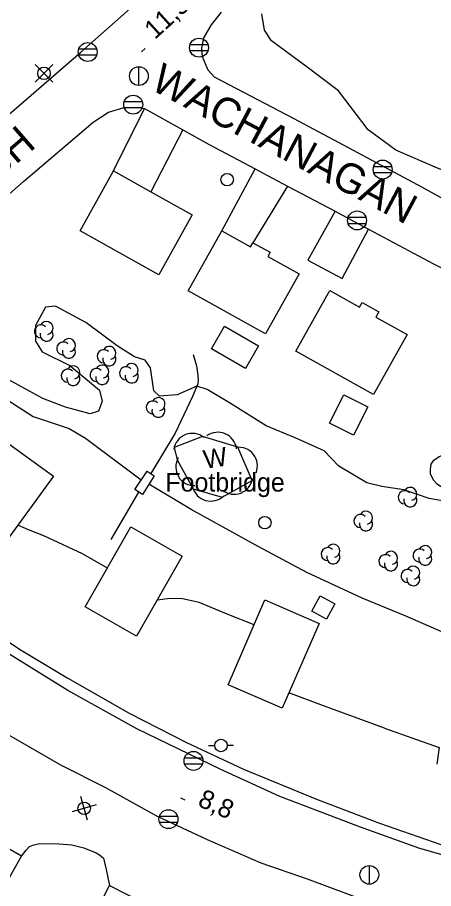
# Model space of a CAD drawing. Extents: x 646142 to 649934, y 5874075 to 5876351.
# Drawn here: x 646717.7 to 646784.5, y 5874712.5 to 5874852.4 of the extents above; entities that cross this region are included whole.
import ezdxf

# ---------------------------------------------------------------- set-up
doc = ezdxf.new("R2010")
doc.units = 0
for name, color, linetype in [('Niveau 1', 7, 'Continuous'), ('Niveau 15', 7, 'Continuous'), ('Niveau 19', 7, 'Continuous'), ('Niveau 2', 7, 'Continuous'), ('Niveau 21', 7, 'Continuous'), ('Niveau 22', 7, 'Continuous'), ('Niveau 26', 7, 'Continuous'), ('Niveau 3', 7, 'Continuous'), ('Niveau 31', 7, 'Continuous'), ('Niveau 36', 7, 'Continuous'), ('Niveau 4', 7, 'Continuous'), ('Niveau 44', 7, 'Continuous')]:
    doc.layers.add(name, color=color, linetype=linetype)

msp = doc.modelspace()

# ---------------------------------------------------------------- linework, layer by layer
at = {"layer": 'Niveau 1'}
for points in [[(646739.02, 5874796.13), (646738.16, 5874797.35), (646736.48, 5874797.92), (646733.65, 5874799.69), (646728.67, 5874803.4), (646723.78, 5874806.06), (646722.16, 5874805.88), (646720.59, 5874802.94), (646720.57, 5874800.42), (646721.64, 5874798.69), (646726.09, 5874796.52), (646730.85, 5874792.56), (646731.29, 5874790.78), (646730.66, 5874789.2), (646729.36, 5874788.75), (646725.41, 5874789.84), (646721.74, 5874791.19), (646716.17, 5874794.27)], [(646787.38, 5874774.53), (646783.77, 5874775.18), (646779.69, 5874776.56), (646776.14, 5874777.1), (646773.76, 5874777.67), (646769.28, 5874780.36), (646766.92, 5874782.81), (646762.25, 5874784.9), (646757.6, 5874786.82), (646751.69, 5874790.51), (646748.13, 5874792.63), (646746.45, 5874793.2), (646743.3, 5874791.78), (646740.45, 5874791.56), (646739.56, 5874792.42), (646739.02, 5874796.13)]]:
    msp.add_lwpolyline(points, dxfattribs=at)
at = {"layer": 'Niveau 19'}
for points in [[(646733.07, 5874827.74), (646738.07, 5874837.74)], [(646744.19, 5874834.36), (646739.1, 5874824.38)], [(646750.45, 5874818.15), (646755.8, 5874828.09)], [(646761.02, 5874825.31), (646755.47, 5874816.22)], [(646768.65, 5874821.27), (646764.29, 5874813.44), (646769.78, 5874810.48), (646774.04, 5874818.4)], [(646732.1, 5874763.98), (646728.1, 5874766.28), (646721.89, 5874769.19), (646719.45, 5874770.15), (646717.72, 5874770.86)], [(646755.67, 5874754.9), (646751.34, 5874756.58), (646746.85, 5874758.45), (646744.15, 5874759.04), (646742.19, 5874759.08), (646740.08, 5874758.84)], [(646776.57, 5874738.28), (646766.36, 5874742.03), (646761.24, 5874743.95)], [(646776.57, 5874738.28), (646785.37, 5874735.17), (646784.96, 5874732.52)], [(646718.33, 5874717.72), (646719.05, 5874718.72), (646719.62, 5874719.27), (646720.13, 5874719.52), (646721.23, 5874719.78), (646724.31, 5874719.71), (646726.38, 5874719.54), (646728.33, 5874719.07), (646730.32, 5874718.3), (646730.84, 5874717.97), (646731.49, 5874717.4), (646731.93, 5874715.59), (646732.45, 5874713.02)]]:
    msp.add_lwpolyline(points, dxfattribs=at)
at = {"layer": 'Niveau 2'}
msp.add_lwpolyline([(646802.57, 5874853.89), (646806.87, 5874850.43), (646809.49, 5874846.9), (646809.96, 5874844.71), (646809.71, 5874842.12), (646808.76, 5874840.24), (646805.83, 5874835.56), (646801.62, 5874829.39), (646798.83, 5874825.84), (646796.78, 5874824.62), (646795.1, 5874824.49), (646791.67, 5874825.8), (646785.07, 5874828.21), (646778.42, 5874831.07), (646773.96, 5874834.35), (646769.19, 5874840.58), (646764.16, 5874844.4), (646758.45, 5874848.63), (646757.32, 5874850.35), (646756.87, 5874852.95)], dxfattribs=at)
at = {"layer": 'Niveau 21'}
for points in [[(646793.63, 5874859.05), (646807.67, 5874851.14), (646809.33, 5874849.4), (646810.83, 5874846.71), (646811.11, 5874844.75), (646810.96, 5874842.4), (646809.15, 5874838.87), (646803.42, 5874827.9), (646799.87, 5874821.54), (646798.56, 5874820.5), (646796.41, 5874819.74), (646794.8, 5874819.5), (646793.14, 5874819.84), (646790.62, 5874820.69), (646782.69, 5874825.09)], [(646657.58, 5874800.59), (646660.09, 5874797.79), (646662, 5874795.83), (646663.59, 5874795.02), (646665.12, 5874794.9), (646666.62, 5874795.14), (646668.79, 5874795.78), (646671.96, 5874798.52), (646674.89, 5874801.06), (646689.07, 5874813.31), (646701.81, 5874824.5), (646714.25, 5874835.07), (646727.87, 5874846.79), (646737.1, 5874855.01)], [(646782.69, 5874825.09), (646771.59, 5874831), (646762.08, 5874836.1), (646749.29, 5874842.82), (646748.26, 5874843.91), (646747.39, 5874846.07), (646747.27, 5874847.46), (646747.6, 5874849.13), (646748.83, 5874851.21), (646750.41, 5874853.21)], [(646706.22, 5874815.11), (646718.62, 5874826.03), (646729.85, 5874835.58), (646732.29, 5874837.17), (646734.79, 5874837.95), (646736.89, 5874838), (646738.07, 5874837.74), (646744.19, 5874834.36), (646748.46, 5874832), (646755.8, 5874828.09), (646758.59, 5874826.6), (646761.02, 5874825.31), (646768.65, 5874821.27), (646770.9, 5874820.08), (646774.04, 5874818.4), (646784.43, 5874812.84), (646788.56, 5874810.82)], [(646850.91, 5874726.13), (646847.96, 5874720.73), (646841.47, 5874708.85), (646840.29, 5874707.58), (646838.49, 5874706.85), (646836.04, 5874706.77), (646825.69, 5874709.11), (646809.68, 5874712.06), (646795.52, 5874715.15), (646782.11, 5874719.01), (646772.72, 5874722.37), (646759.8, 5874727.32), (646750.2, 5874731.72), (646736.81, 5874738.16), (646725.78, 5874744.32), (646707.8, 5874755.44)], [(646714.15, 5874738.37), (646724.58, 5874732.4), (646731.78, 5874728.75), (646739.98, 5874724.24), (646748.13, 5874720.43), (646756.74, 5874716.66), (646764.19, 5874714.09), (646774.08, 5874710.42)]]:
    msp.add_lwpolyline(points, dxfattribs=at)
at = {"layer": 'Niveau 22'}
for points in [[(646745.9, 5874798.25), (646746.39, 5874796.45), (646746.55, 5874795.34), (646746.66, 5874794.33), (646746.6, 5874793.55), (646745.79, 5874791.51), (646742.96, 5874785.65), (646739.09, 5874779.16)], [(646732.7, 5874768.56), (646737.15, 5874776.18)], [(646712.61, 5874754.48), (646718.25, 5874750.81), (646725.76, 5874746.31), (646735.6, 5874740.72), (646744.79, 5874736.01), (646753.96, 5874731.73), (646765.66, 5874726.87), (646775.76, 5874723.06), (646785.61, 5874719.61), (646793.54, 5874717.4), (646802.06, 5874715.33), (646813.83, 5874712.84), (646819.54, 5874711.71), (646829.83, 5874709.74), (646837.05, 5874708.42), (646838.55, 5874708.53), (646840.1, 5874708.87), (646841.85, 5874709.54)]]:
    msp.add_lwpolyline(points, dxfattribs=at)
at = {"layer": 'Niveau 26'}
msp.add_lwpolyline([(646739.61, 5874778.82), (646737.74, 5874775.8), (646736.5, 5874776.62), (646738.5, 5874779.54), (646739.61, 5874778.82), (646739.61, 5874778.82)], dxfattribs=at)
at = {"layer": 'Niveau 3'}
for p, q in [((646737.57, 5874846.86), (646738.16, 5874847.4)), ((646743.82, 5874727.08), (646744.55, 5874726.76))]:
    msp.add_line(p, q, dxfattribs=at)
at = {"layer": 'Niveau 31'}
for points in [[(646740.38, 5874811.07), (646727.72, 5874818.12), (646733.07, 5874827.74), (646739.1, 5874824.38), (646745.74, 5874820.69), (646740.38, 5874811.07)], [(646757.49, 5874801.57), (646745.07, 5874808.52), (646750.45, 5874818.15), (646755.1, 5874815.55), (646755.47, 5874816.22), (646758.21, 5874814.69), (646757.84, 5874814.02), (646762.88, 5874811.21), (646757.49, 5874801.57)], [(646774.84, 5874791.87), (646762.36, 5874798.81), (646767.79, 5874808.56), (646772.59, 5874805.88), (646772.99, 5874806.62), (646775.68, 5874805.12), (646775.21, 5874804.29), (646780.21, 5874801.51), (646774.84, 5874791.87)], [(646754.26, 5874796.03), (646748.83, 5874799.17), (646750.92, 5874802.81), (646756.36, 5874799.67), (646754.26, 5874796.03)], [(646773.91, 5874789.88), (646771.61, 5874785.32), (646767.75, 5874787.27), (646770.05, 5874791.82), (646773.91, 5874789.88)], [(646706.97, 5874772.35), (646715.7, 5874784.38), (646723.45, 5874778.75), (646714.71, 5874766.73), (646706.97, 5874772.35)], [(646786.22, 5874782.22), (646786.86, 5874782.21), (646787.88, 5874781.77), (646788.83, 5874780.91), (646789.25, 5874780.01), (646789.31, 5874779.31), (646788.76, 5874778.21), (646787.5, 5874777.18), (646786.59, 5874776.99), (646785.59, 5874777.09), (646785.04, 5874777.45), (646784.46, 5874778.11), (646783.97, 5874779.12), (646783.96, 5874779.88), (646784.07, 5874780.65), (646784.48, 5874781.32), (646785.37, 5874781.92), (646786.22, 5874782.22)], [(646728.56, 5874757.76), (646735.88, 5874770.61), (646744.11, 5874765.91), (646736.79, 5874753.07), (646728.56, 5874757.76)], [(646766.24, 5874759.51), (646768.62, 5874758.24), (646767.3, 5874755.78), (646764.92, 5874757.05), (646766.24, 5874759.51)], [(646751.48, 5874745.27), (646757.4, 5874758.88), (646766.09, 5874755.11), (646760.17, 5874741.49), (646751.48, 5874745.27)], [(646718.33, 5874717.72), (646702.44, 5874726.89), (646698.77, 5874720.54), (646714.67, 5874711.37), (646718.33, 5874717.72)], [(646740.97, 5874708.68), (646734.2, 5874695.39), (646725.68, 5874699.73), (646732.45, 5874713.02), (646740.97, 5874708.68)]]:
    msp.add_lwpolyline(points, dxfattribs=at)
at = {"layer": 'Niveau 36'}
for p, q in [((646730.39, 5874847.28), (646727.51, 5874847.28)), ((646748.25, 5874847.98), (646745.37, 5874847.98)), ((646745.37, 5874847.06), (646748.25, 5874847.06)), ((646727.51, 5874846.36), (646730.39, 5874846.36)), ((646723.34, 5874842), (646720.52, 5874844.82)), ((646720.52, 5874842), (646723.34, 5874844.82)), ((646737.17, 5874841.46), (646737.17, 5874844.46)), ((646737.69, 5874838.84), (646734.81, 5874838.84)), ((646734.81, 5874837.92), (646737.69, 5874837.92)), ((646777.73, 5874828.41), (646774.85, 5874828.41)), ((646774.85, 5874827.49), (646777.73, 5874827.49)), ((646773.62, 5874820.25), (646770.74, 5874820.25)), ((646770.74, 5874819.33), (646773.62, 5874819.33)), ((646748.35, 5874735.5), (646749.35, 5874735.5)), ((646752.35, 5874735.5), (646751.35, 5874735.5)), ((646747.37, 5874733.48), (646744.49, 5874733.48)), ((646744.49, 5874732.56), (646747.37, 5874732.56)), ((646728.93, 5874723.51), (646727.84, 5874727.34)), ((646730.3, 5874725.97), (646726.47, 5874724.88)), ((646743.35, 5874724.13), (646740.47, 5874724.13)), ((646740.47, 5874723.21), (646743.35, 5874723.21)), ((646774.16, 5874713.23), (646774.16, 5874716.23))]:
    msp.add_line(p, q, dxfattribs=at)
for centre, radius in [((646746.81, 5874847.53), 1.52), ((646728.95, 5874846.83), 1.52), ((646721.93, 5874843.41), 1), ((646737.16, 5874842.97), 1.5), ((646736.25, 5874838.39), 1.52), ((646776.29, 5874827.96), 1.52), ((646751.34, 5874826.33), 1), ((646772.18, 5874819.8), 1.52), ((646757.39, 5874771.28), 1), ((646750.34, 5874735.5), 1), ((646745.93, 5874733.03), 1.52), ((646728.38, 5874725.43), 1), ((646741.91, 5874723.68), 1.52), ((646774.15, 5874714.74), 1.5)]:
    msp.add_circle(centre, radius, dxfattribs=at)
at = {"layer": 'Niveau 4'}
for points in [[(646701.09, 5874804.73), (646704.3, 5874801.35), (646709.03, 5874796.44), (646713.68, 5874792.47), (646720.22, 5874788.3), (646725.99, 5874786.41), (646728.57, 5874784.85), (646737.55, 5874778.14)], [(646807.06, 5874745.6), (646795.63, 5874749.7), (646787.89, 5874752.84), (646779.89, 5874756.31), (646773, 5874759.16), (646764.13, 5874763.27), (646756.31, 5874767.46), (646745.53, 5874773.41), (646738.75, 5874777.44)]]:
    msp.add_lwpolyline(points, dxfattribs=at)
at = {"layer": 'Niveau 44'}
msp.add_lwpolyline([(646743.33, 5874781.38), (646745.87, 5874776.72), (646750.53, 5874775.37), (646755.33, 5874778.06), (646753.07, 5874783.39), (646747.35, 5874785.13), (646742.83, 5874783.37), (646743.33, 5874781.38)], dxfattribs=at)
for centre, radius, start, end in [((646721.44, 5874801.99), 1.05, 44.1154, 269.804), ((646722.34, 5874802.52), 1.05, 282.2692, 149.7263), ((646722.34, 5874801.47), 1.05, 166.9369, 29.6212), ((646725.03, 5874799.24), 1.05, 44.1154, 269.804), ((646725.93, 5874799.77), 1.05, 282.2692, 149.7263), ((646732.42, 5874798.53), 1.05, 282.2692, 149.7263), ((646725.93, 5874798.72), 1.05, 166.9369, 29.6212), ((646731.52, 5874798), 1.05, 44.1154, 269.804), ((646732.42, 5874797.48), 1.05, 166.9369, 29.6212), ((646736.01, 5874795.79), 1.05, 282.2692, 149.7263), ((646725.74, 5874794.87), 1.05, 44.1154, 269.804), ((646726.64, 5874795.4), 1.05, 282.2692, 149.7263), ((646730.38, 5874795), 1.05, 44.1154, 269.804), ((646731.28, 5874795.53), 1.05, 282.2692, 149.7263), ((646735.11, 5874795.26), 1.05, 44.1154, 269.804), ((646726.64, 5874794.35), 1.05, 166.9369, 29.6212), ((646731.28, 5874794.48), 1.05, 166.9369, 29.6212), ((646736.01, 5874794.74), 1.05, 166.9369, 29.6212), ((646740.3, 5874790.3), 1.05, 282.2692, 149.7263), ((646739.4, 5874789.77), 1.05, 44.1154, 269.804), ((646740.3, 5874789.25), 1.05, 166.9369, 29.6212), ((646745.73, 5874782.61), 3, 51.3082, 171.2861), ((646749.85, 5874782.79), 3, 6.7921, 126.77), ((646753.19, 5874780.39), 3, 338.2691, 98.2471), ((646746.1, 5874780.22), 3, 151.1818, 271.1598), ((646752.43, 5874778.84), 3, 230.9258, 350.9037), ((646748.69, 5874777.74), 3, 193.9383, 313.9162), ((646779.83, 5874775.36), 1.05, 44.1154, 269.804), ((646780.73, 5874775.89), 1.05, 282.2692, 149.7263), ((646780.73, 5874774.84), 1.05, 166.9369, 29.6212), ((646773.62, 5874772.07), 1.05, 282.2692, 149.7263), ((646772.72, 5874771.54), 1.05, 44.1154, 269.804), ((646773.62, 5874771.02), 1.05, 166.9369, 29.6212), ((646768.37, 5874766.76), 1.05, 282.2692, 149.7263), ((646783.12, 5874766.54), 1.05, 282.2692, 149.7263), ((646767.47, 5874766.23), 1.05, 44.1154, 269.804), ((646768.37, 5874765.71), 1.05, 166.9369, 29.6212), ((646776.73, 5874765.1), 1.05, 44.1154, 269.804), ((646777.63, 5874765.63), 1.05, 282.2692, 149.7263), ((646782.22, 5874766.01), 1.05, 44.1154, 269.804), ((646783.12, 5874765.49), 1.05, 166.9369, 29.6212), ((646777.63, 5874764.58), 1.05, 166.9369, 29.6212), ((646780.29, 5874762.72), 1.05, 44.1154, 269.804), ((646781.19, 5874763.25), 1.05, 282.2692, 149.7263), ((646781.19, 5874762.2), 1.05, 166.9369, 29.6212)]:
    msp.add_arc(centre, radius, start, end, dxfattribs=at)

# ---------------------------------------------------------------- texts
at = {"layer": 'Niveau 15'}
for s, rotation, p in [('WACHANAGAN', 332.0654, (646738.8, 5874840.97)), ('GEORGEKISH', 41.0604, (646688.33, 5874803.36))]:
    msp.add_text(s, height=4.8, rotation=rotation, dxfattribs=at).set_placement(p)
at = {"layer": 'Niveau 26'}
msp.add_text('Footbridge', height=3, dxfattribs=at).set_placement((646741.4, 5874776.27))
at = {"layer": 'Niveau 3'}
for s, rotation, p in [('11,5 ', 42.1523, (646739.73, 5874848.76)), ('8,8  ', 335.9831, (646746.44, 5874725.88))]:
    msp.add_text(s, height=3, rotation=rotation, dxfattribs=at).set_placement(p)
at = {"layer": 'Niveau 44'}
msp.add_text('W', height=3, rotation=8.9405, dxfattribs=at).set_placement((646747.77, 5874779.9))

doc.saveas('drawing.dxf')
